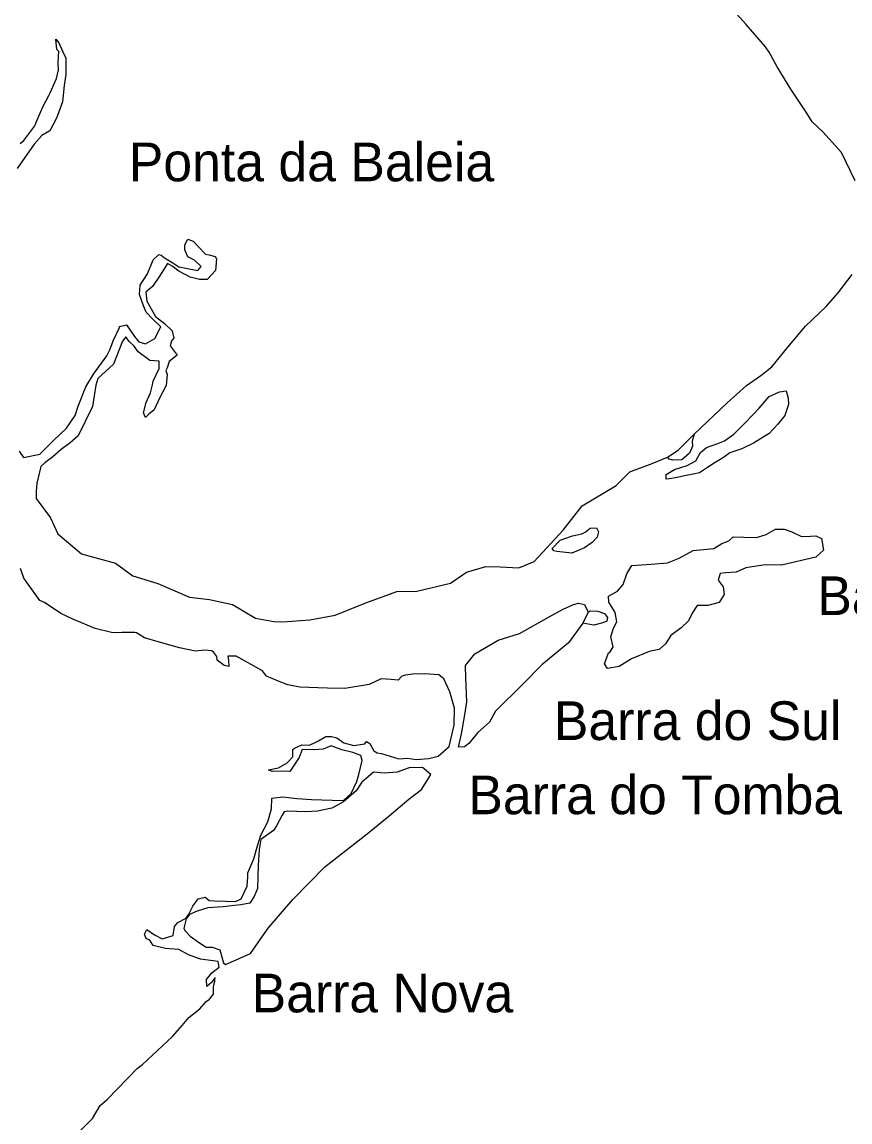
# Model space of a CAD drawing. Extents: x 662444 to 1640468, y 7452018 to 9606170.
# Drawn here: x 1108329 to 1122322, y 8019615 to 8038208 of the extents above; entities that cross this region are included whole.
import ezdxf

# ---------------------------------------------------------------- set-up
doc = ezdxf.new("R2010")
doc.units = 0
doc.layers.add('Level 1', color=7, linetype='Continuous')
doc.layers.add('Level 3', color=7, linetype='Continuous')

msp = doc.modelspace()

# ---------------------------------------------------------------- linework, layer by layer
at = {"layer": 'Level 1'}
for points in [[(1122409, 8035522), (1122176, 8036001), (1121862, 8036351), (1121682, 8036519), (1121594, 8036669), (1121320, 8037072), (1121093, 8037450), (1120954, 8037695), (1120895, 8037790), (1120566, 8038164), (1120133, 8038649)], [(1108298, 8036152), (1108361, 8036205), (1108547, 8036454), (1108564, 8036500), (1108680, 8036774), (1108780, 8036964), (1108803, 8037010), (1108912, 8037253), (1108947, 8037399), (1108943, 8037508), (1108947, 8037631), (1108949, 8037708), (1108919, 8037740), (1108901, 8037919), (1108954, 8037856), (1109019, 8037706), (1109070, 8037597), (1109069, 8037319), (1109040, 8037134), (1109015, 8036857), (1108914, 8036582), (1108799, 8036368), (1108665, 8036288), (1108537, 8036145), (1108245, 8035729)], [(1110313, 8033599), (1110326, 8033761), (1110448, 8033951), (1110548, 8034187), (1110644, 8034277), (1110682, 8034268), (1110735, 8034220), (1110879, 8034138), (1110978, 8034072), (1111100, 8034045), (1111209, 8034026), (1111301, 8034008), (1111356, 8034076), (1111244, 8034180), (1111130, 8034238), (1111079, 8034355), (1111082, 8034440), (1111132, 8034539), (1111223, 8034505), (1111313, 8034410), (1111433, 8034282), (1111494, 8034272), (1111594, 8034246), (1111616, 8034207), (1111602, 8034006), (1111458, 8033856), (1111327, 8033853), (1111173, 8033896), (1110968, 8034004), (1110878, 8034075), (1110786, 8034125), (1110729, 8034034), (1110655, 8033913), (1110534, 8033739), (1110423, 8033642), (1110441, 8033487), (1110587, 8033227), (1110738, 8033114), (1110867, 8032986), (1110894, 8032862), (1110853, 8032816), (1110835, 8032732), (1110902, 8032645), (1110954, 8032574), (1110819, 8032470), (1110785, 8032362), (1110760, 8032318), (1110781, 8032247), (1110768, 8032062), (1110653, 8031849), (1110561, 8031651), (1110474, 8031577), (1110418, 8031524), (1110382, 8031603), (1110427, 8031778), (1110501, 8031939), (1110536, 8032076), (1110545, 8032138), (1110646, 8032352), (1110649, 8032476), (1110487, 8032488), (1110291, 8032633), (1110225, 8032729), (1110142, 8032808), (1110082, 8032888), (1110026, 8032813), (1109874, 8032423), (1109611, 8032184), (1109577, 8032069), (1109520, 8031707), (1109280, 8031213), (1109144, 8031093), (1108993, 8030982), (1108851, 8030855), (1108716, 8030759), (1108645, 8030692), (1108582, 8030415), (1108570, 8030276), (1108566, 8030153), (1108811, 8029829), (1108934, 8029554), (1109333, 8029217), (1109907, 8029059), (1110203, 8028849), (1110624, 8028719), (1111158, 8028486), (1111497, 8028444), (1111888, 8028362), (1112276, 8028133), (1112583, 8028077)], [(1112583, 8028077), (1112737, 8028071), (1113194, 8028104), (1113622, 8028182), (1114139, 8028389), (1114663, 8028582), (1115004, 8028586), (1115572, 8028722), (1115841, 8028907), (1116169, 8029005), (1116408, 8028998), (1116724, 8028979), (1116983, 8029087), (1117472, 8029620), (1117794, 8030027), (1118369, 8030371), (1118601, 8030603), (1118977, 8030746), (1119236, 8030854), (1119417, 8030972), (1119688, 8031241), (1120247, 8031772), (1120573, 8032063), (1120818, 8032233), (1121001, 8032381), (1121274, 8032713), (1121572, 8033067), (1121922, 8033396), (1122124, 8033629), (1122358, 8033938)], [(1108282, 8030951), (1108355, 8030848), (1108628, 8030901), (1108860, 8031134), (1109082, 8031343), (1109228, 8031554), (1109280, 8031715), (1109406, 8032043), (1109537, 8032256), (1109762, 8032565), (1109812, 8032665), (1109871, 8032817), (1109978, 8033045), (1109979, 8033061), (1110096, 8033088), (1110230, 8032891), (1110304, 8032803), (1110419, 8032768), (1110576, 8032856), (1110675, 8033054), (1110540, 8033183), (1110428, 8033302), (1110385, 8033411), (1110313, 8033599)], [(1120546, 8031429), (1120676, 8031563), (1120789, 8031683), (1120954, 8031879), (1121128, 8031955), (1121244, 8031972), (1121275, 8031849), (1121282, 8031741), (1121220, 8031559), (1121102, 8031412), (1120955, 8031253), (1120694, 8031090), (1120496, 8030991), (1120294, 8030924), (1120182, 8030848), (1120046, 8030761), (1119914, 8030678), (1119780, 8030590), (1119674, 8030562), (1119527, 8030534), (1119404, 8030509), (1119272, 8030486), (1119214, 8030482), (1119218, 8030559), (1119359, 8030644), (1119571, 8030711), (1119714, 8030789), (1119796, 8030929), (1119899, 8031018), (1120087, 8031083), (1120204, 8031128), (1120358, 8031241), (1120546, 8031429)], [(1119688, 8031241), (1119654, 8031125), (1119658, 8031039), (1119609, 8030917), (1119482, 8030808), (1119324, 8030801), (1119268, 8030818), (1119236, 8030854)], [(1117837, 8029319), (1117621, 8029229), (1117369, 8029255), (1117315, 8029270), (1117291, 8029311), (1117423, 8029448), (1117630, 8029520), (1117790, 8029556), (1117845, 8029582), (1117933, 8029654), (1118039, 8029658), (1118072, 8029588), (1118047, 8029499), (1117967, 8029410), (1117837, 8029319)], [(1119433, 8029147), (1119669, 8029275), (1120021, 8029310), (1120157, 8029393), (1120274, 8029438), (1120349, 8029505), (1120529, 8029501), (1120743, 8029495), (1120906, 8029546), (1121065, 8029636), (1121208, 8029636), (1121338, 8029588), (1121504, 8029509), (1121657, 8029517), (1121742, 8029524), (1121838, 8029478), (1121875, 8029278), (1121743, 8029162), (1121167, 8029026), (1120886, 8029035), (1120561, 8028982), (1120400, 8028908), (1120226, 8028896), (1120128, 8028888), (1120096, 8028774), (1120180, 8028661), (1120196, 8028531), (1120110, 8028395), (1119920, 8028346), (1119740, 8028344), (1119654, 8028213), (1119594, 8028087), (1119470, 8027970), (1119292, 8027838), (1119203, 8027699), (1119095, 8027600), (1118926, 8027569), (1118630, 8027445), (1118423, 8027314), (1118225, 8027280), (1118171, 8027357), (1118239, 8027542), (1118270, 8027564), (1118319, 8027644), (1118278, 8027816), (1118326, 8027961), (1118381, 8028067), (1118353, 8028228), (1118247, 8028400), (1118243, 8028502), (1118392, 8028589), (1118488, 8028699), (1118549, 8028881), (1118638, 8029022), (1118961, 8029044), (1119236, 8029067), (1119433, 8029147)], [(1114195, 8027012), (1113784, 8026940), (1113490, 8026949), (1113328, 8026954), (1113027, 8026965), (1112819, 8027002), (1112674, 8027061), (1112461, 8027152), (1112394, 8027240), (1111946, 8027486), (1111806, 8027491), (1111820, 8027413), (1111824, 8027312), (1111748, 8027330), (1111627, 8027419), (1111620, 8027482), (1111569, 8027552), (1111539, 8027577), (1111415, 8027588), (1111260, 8027571), (1110991, 8027632), (1110632, 8027729), (1110402, 8027798), (1110265, 8027880), (1110234, 8027889), (1110018, 8027888), (1109932, 8027883), (1109840, 8027886), (1109564, 8027956), (1109190, 8028116), (1108984, 8028208), (1108712, 8028394), (1108628, 8028428), (1108361, 8028807), (1108304, 8028971)], [(1115811, 8026496), (1115848, 8026718), (1115830, 8027122), (1115822, 8027331), (1115982, 8027526), (1116376, 8027761), (1116736, 8027873), (1117240, 8028151), (1117475, 8028283), (1117648, 8028362), (1117734, 8028383), (1117834, 8028364), (1117899, 8028230), (1117808, 8028048), (1117565, 8027715), (1117114, 8027343), (1116801, 8027020), (1116330, 8026557), (1116232, 8026374), (1116033, 8026196), (1115880, 8026015), (1115809, 8025955), (1115708, 8025950), (1115754, 8026173), (1115811, 8026496)], [(1117899, 8028230), (1117939, 8028252), (1118063, 8028250), (1118175, 8028208), (1118222, 8028143), (1118215, 8028082), (1118145, 8028053), (1117992, 8028010), (1117808, 8028048)], [(1111587, 8021994), (1111588, 8022041), (1111596, 8022055), (1111532, 8021972), (1111453, 8021906), (1111448, 8022022), (1111537, 8022135), (1111663, 8022231), (1111644, 8022325), (1111343, 8022365), (1111144, 8022441), (1110978, 8022531), (1110754, 8022547), (1110546, 8022599), (1110487, 8022686), (1110427, 8022719), (1110398, 8022789), (1110440, 8022866), (1110568, 8022776), (1110697, 8022711), (1110885, 8022766), (1110905, 8022920), (1110961, 8022987), (1111103, 8023061), (1111151, 8023128), (1111217, 8023265), (1111306, 8023387), (1111423, 8023414), (1111490, 8023357), (1111583, 8023354), (1111761, 8023349), (1111938, 8023343), (1112032, 8023387), (1112132, 8023600), (1112145, 8023762), (1112147, 8023824), (1112247, 8024060), (1112308, 8024282), (1112368, 8024465), (1112484, 8024686), (1112545, 8024908), (1112550, 8025086), (1112736, 8025111), (1112975, 8025080), (1113222, 8025064), (1113569, 8025053), (1113763, 8025047), (1113890, 8025167), (1113989, 8025372), (1114023, 8025487), (1114078, 8025725), (1114057, 8025811), (1113920, 8025861), (1113736, 8025905), (1113553, 8025973), (1113419, 8025916), (1113271, 8025905), (1113063, 8025912), (1113013, 8025774), (1112858, 8025540), (1112719, 8025544), (1112557, 8025541), (1112496, 8025567), (1112666, 8025600), (1112809, 8025688), (1112904, 8025785), (1112908, 8025910), (1112932, 8025931), (1113058, 8025990), (1113190, 8025986), (1113338, 8026058), (1113465, 8026131), (1113557, 8026128), (1113649, 8026109), (1113770, 8026021), (1113938, 8025977), (1114125, 8026009), (1114149, 8026047), (1114210, 8026014), (1114276, 8025889), (1114329, 8025856), (1114406, 8025846), (1114696, 8025751), (1114844, 8025762), (1114990, 8025742), (1115207, 8025757), (1115363, 8025799), (1115546, 8025964), (1115635, 8026324), (1115636, 8026609), (1115560, 8026883), (1115459, 8027103), (1115376, 8027175), (1115136, 8027191), (1114928, 8027182), (1114812, 8027170), (1114749, 8027148), (1114685, 8027081), (1114570, 8027093), (1114400, 8027106), (1114195, 8027012)], [(1111721, 8022345), (1111736, 8022306), (1111766, 8022274), (1112189, 8022461), (1112488, 8022892), (1112905, 8023373), (1113449, 8023928), (1114162, 8024485), (1114535, 8024790), (1114868, 8025073), (1115082, 8025236), (1115204, 8025433), (1115237, 8025486), (1115095, 8025606), (1114870, 8025599), (1114667, 8025528), (1114449, 8025512), (1114272, 8025525), (1114177, 8025451), (1114074, 8025361), (1113976, 8025210), (1113762, 8025024), (1113565, 8024922), (1113323, 8024868), (1113123, 8024859), (1112976, 8024863), (1112822, 8024868), (1112759, 8024855), (1112727, 8024802), (1112628, 8024620), (1112579, 8024544), (1112366, 8024389), (1112337, 8024219), (1112321, 8023950), (1112315, 8023764), (1112308, 8023563), (1112250, 8023426), (1112177, 8023312), (1112029, 8023286), (1111921, 8023274), (1111727, 8023250), (1111471, 8023234), (1111292, 8023178), (1111162, 8023120), (1111104, 8023048), (1111067, 8022915), (1111065, 8022884), (1111088, 8022844), (1111170, 8022757), (1111314, 8022652), (1111442, 8022570), (1111543, 8022567), (1111673, 8022524), (1111721, 8022345)], [(1109129, 8019274), (1109519, 8019671), (1109650, 8019892), (1109770, 8019996), (1110273, 8020521), (1110367, 8020587), (1110870, 8021059), (1111037, 8021246), (1111150, 8021381), (1111333, 8021530), (1111444, 8021650), (1111499, 8021688), (1111564, 8021778), (1111568, 8021901), (1111587, 8021994)]]:
    msp.add_lwpolyline(points, dxfattribs=at)

# ---------------------------------------------------------------- texts
at = {"layer": 'Level 3'}
for s, height, p in [('Ponta da Baleia', 654, (1110134, 8035515)), ('Barra Leste', 653.88, (1121770, 8028183)), ('Barra do Sul', 653.76, (1117318, 8026071)), ('Barra do Tomba', 653.71, (1115873, 8024817)), ('Barra Nova', 653.5, (1112211, 8021468))]:
    msp.add_text(s, height=height, dxfattribs=at).set_placement(p)

doc.saveas('drawing.dxf')
